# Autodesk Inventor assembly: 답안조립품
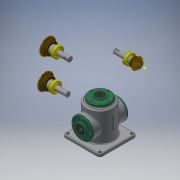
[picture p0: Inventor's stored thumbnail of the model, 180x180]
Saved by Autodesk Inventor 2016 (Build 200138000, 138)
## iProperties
Created: 2019-08
Part Number: 답안조립품
Material: 일반
Document SubType Name: Assembly
Designer: user
Author: user
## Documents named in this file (16)
- D:\490823V1014\답안조립품.iam
- D:\490823V1014\본체.ipt
- D:\490823V1014\메인 베벨기어.ipt
- D:\490823V1014\메인 축.ipt
- 메인 축.ipt
- D:\490823V1014\베어링 6203.ipt
- D:\490823V1014\볼트 M4.ipt
- 볼트 M4.ipt
- D:\490823V1014\서브 베벨기어.ipt
- D:\490823V1014\서브 축.ipt
- 서브 축.ipt
- D:\490823V1014\오일 실.ipt
- 오일 실.ipt
- D:\490823V1014\커버.ipt
- D:\490823V1014\키 4x4.ipt
- D:\490823V1014\키 5x5.ipt
